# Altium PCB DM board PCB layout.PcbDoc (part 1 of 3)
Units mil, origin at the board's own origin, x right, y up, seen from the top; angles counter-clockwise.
Board outline 4444 x 6127 mil, 2 copper layers (Top Layer, Bottom Layer); 112 components, 94 nets, 2801 pads, 141 vias.
Unrouted connection lines stored in the file: 2.
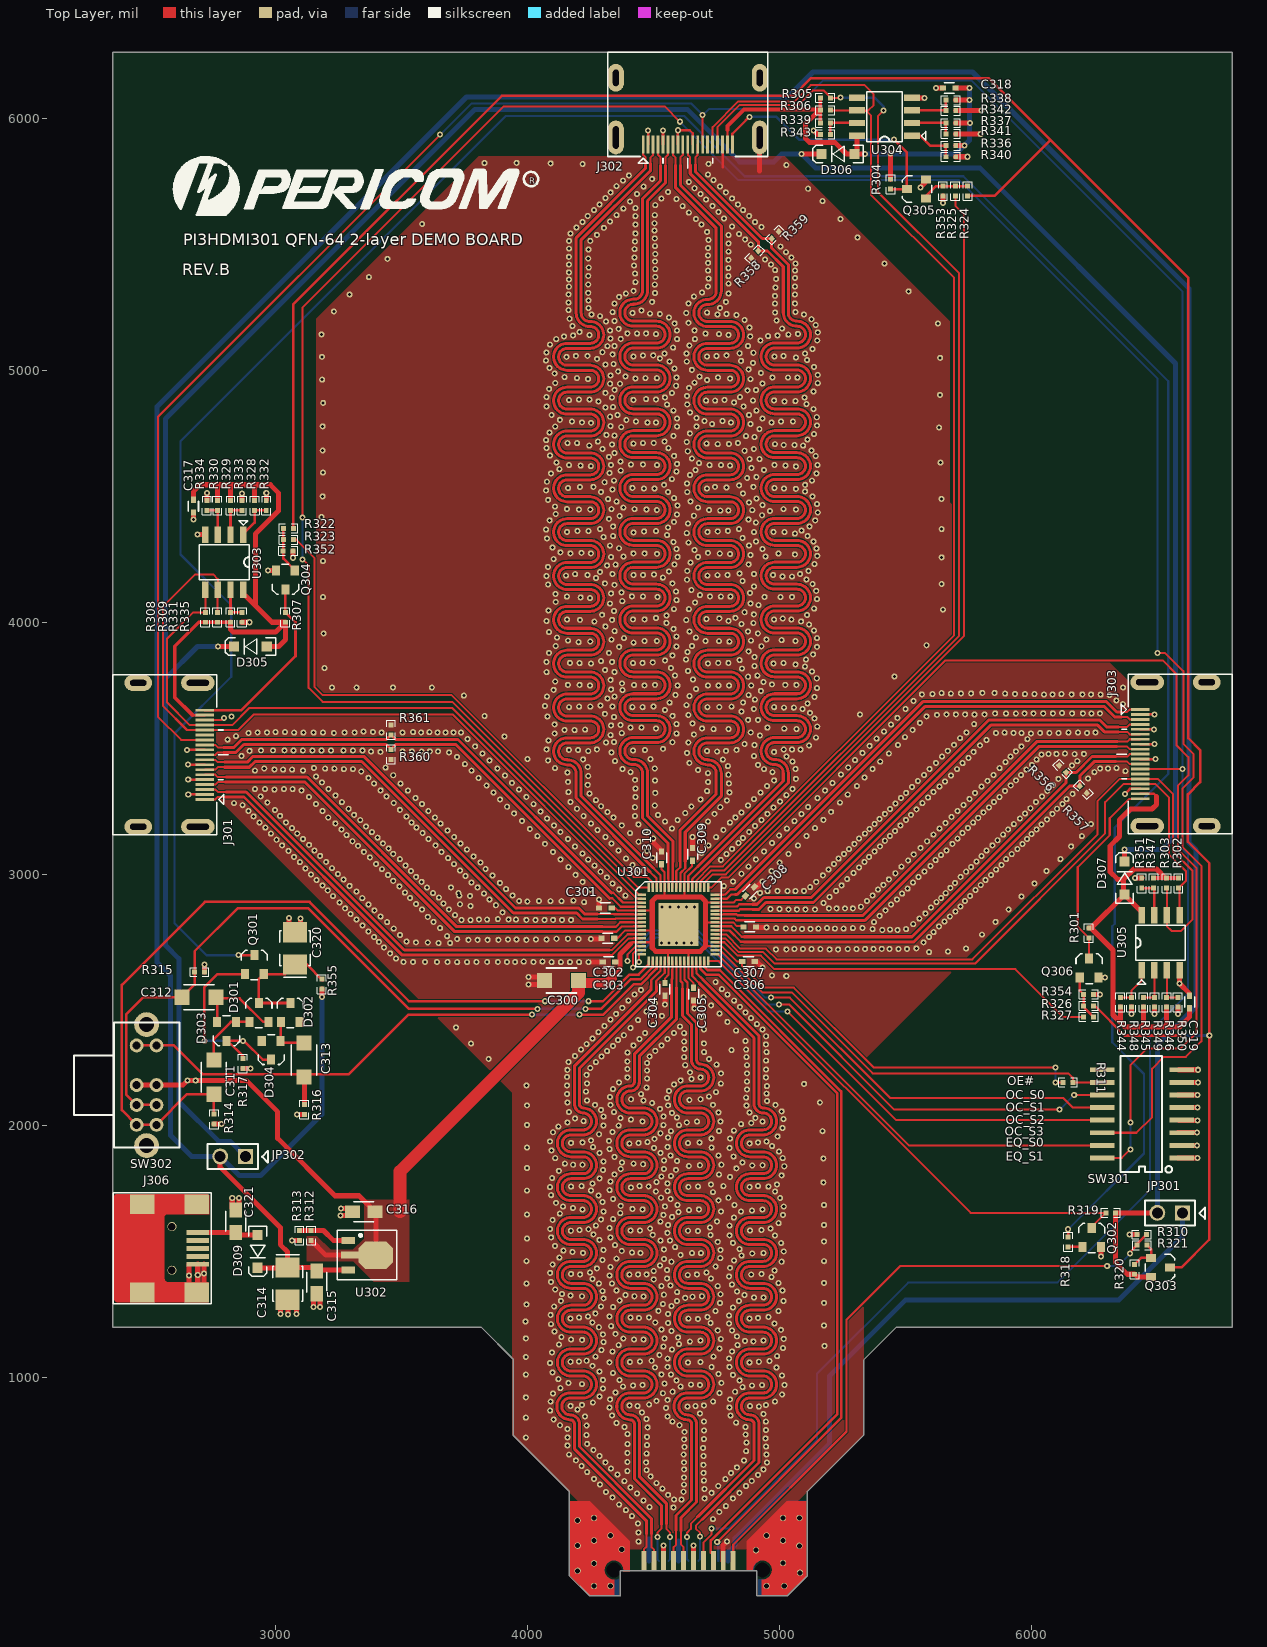
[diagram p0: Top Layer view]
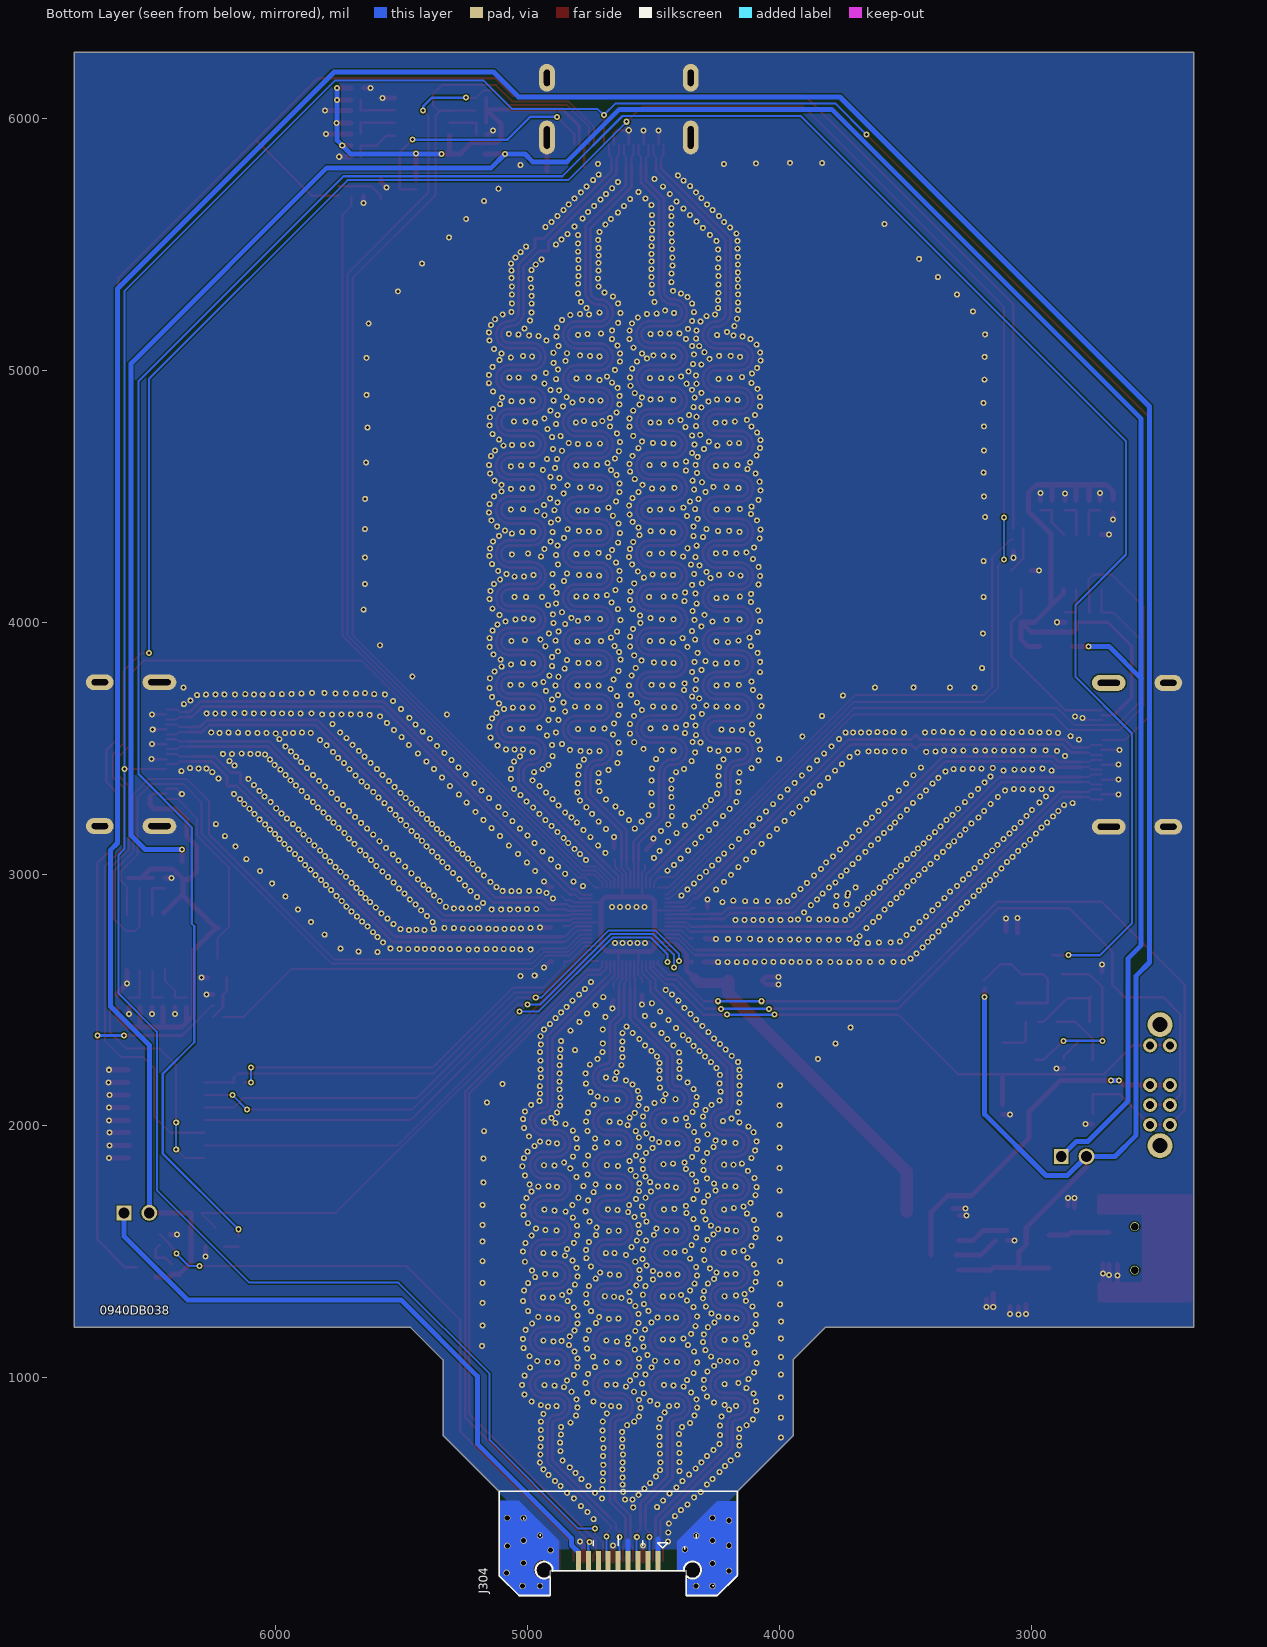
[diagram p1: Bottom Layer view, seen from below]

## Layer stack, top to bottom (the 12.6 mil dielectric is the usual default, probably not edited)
Top Layer: signal copper 1.4
Dielectric: dielectric 12.6, FR-4, Dk 4.8
Bottom Layer: signal copper 1.4

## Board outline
4166,216 4166,550 3944,772 3944,1074 3818,1200 2355,1200 2355,6262 6799,6262 6799,1200 5464,1200 5335,1071 5335,772 5112,549 5112,215 5032,135 4910,135 4910,234 4370,234 4370,136 4369,135 4247,135

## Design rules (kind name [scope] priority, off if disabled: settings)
Clearance [All] p1: gap=5
ComponentClearance [All] p1 off: gap=0 collisioncheckmode=3 verticalgap=0
DiffPairsRouting [All] p1: maxlimit=10 minlimit=8 mostfreqgap=10 toplayer_maxgap=8 toplayer_prefgap=8 bottomlayer_maxgap=8 bottomlayer_prefgap=8 maxuncoupledlength=500
HoleSize [All] p1: absolutevalues=TRUE maxlimit=300 minlimit=1 maxpercent=80.000 minpercent=20.000
PlaneConnect [All] p1: planeconnectstyle=Direct reliefexpansion=20 reliefentries=4 reliefconductorwidth=10 reliefairgap=10
PolygonConnect [All] p1: connectstyle=Direct reliefconductorwidth=10 reliefentries=4 polygonreliefangle="90 Angle"
RoomDefinition "301 (QFN-64) HDMI-HDMI" [InComponentClass('301 (QFN-64) HDMI-HDMI ')] p1: confinementstyle=ConfineIn formatcopy=TRUE lockcomponents=FALSE outline 35,830 43440,830 43440,12870 35,12870
RoutingVias [All] p1: holewidth=28 width=50 viastyle="Through Hole" minholewidth=8 minwidth=10 maxholewidth=28 maxwidth=50
SolderMaskExpansion [All] p1: expansion=4
TestPointUsage [All] p1: valid=0 allowmultiple=FALSE
Testpoint [All] p1: side=15 testpointundercomponent=TRUE minsize=40 maxsize=100 preferedsize=60 minholesize=0 maxholesize=40 preferedholesize=32 testpointgrid=1 style=1023 order=0123456789
Width [All] p1: maxlimit=100 minlimit=6 preferedwidth=10
15 further rules are at their usual default settings.

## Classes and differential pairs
differential pair NewDifferentialPair16: +D33+ -D33-
differential pair NewDifferentialPair15: +D32+ -D32-
differential pair NewDifferentialPair14: +D31+ -D31-
differential pair NewDifferentialPair13: +D3+ -D3-
differential pair NewDifferentialPair12: +D23+ -D23-
differential pair NewDifferentialPair11: +D22+ -D22-
differential pair NewDifferentialPair10: +D21+ -D21-
differential pair NewDifferentialPair9: +D2+ -D2-
differential pair NewDifferentialPair8: +D13+ -D13-
differential pair NewDifferentialPair7: +D12+ -D12-
differential pair NewDifferentialPair6: +D11+ -D11-
differential pair NewDifferentialPair5: +D1+ -D1-
differential pair NewDifferentialPair4: +D03+ -D03-
differential pair NewDifferentialPair3: +D02+ -D02-
differential pair NewDifferentialPair2: +D01+ -D01-
differential pair NewDifferentialPair1: +D0+ -D0-

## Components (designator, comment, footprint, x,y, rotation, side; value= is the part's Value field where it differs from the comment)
C300 "10U" CC_1206 4136,2577 r180 top
C301 "10n" CAP@CC_0402 4310,2865 r180 top
C302 "10n" CAP@CC_0402 4320,2745 r180 top
C303 "10n" CAP@CC_0402 4324,2651 r180 top
C304 "10n" CAP@CC_0402 4546,2542 r270 top
C305 "10n" CAP@CC_0402 4660,2523 r270 top
C306 "10n" CAP@CC_0402 4878,2652 r0 top
C307 "10n" CAP@CC_0402 4883,2790 r0 top
C308 "10n" CAP@CC_0402 4884,2931 r45 top
C309 "10n" CAP@CC_0402 4656,3078 r90 top
C310 "10n" CAP@CC_0402 4533,3064 r90 top
C311 "9.4u" CAP@CC_1206 2756,2193.5 r90 top
C312 "9.4u" CAP@CC_1206 2697,2511 r0 top
C313 "9.4u" CAP@CC_1206 3114,2262 r90 top
C314 "22u" CAP@CT_3528 3049,1374 r270 top
C315 "1u" CAP@CC_0805 3165,1379 r90 top
C316 "1u" CAP@CC_0805 3351,1659 r0 top
C317 "0.1u" CAP@CC_0402 2675,4460 r270 top
C318 "0.1u" CAP@CC_0402 5675,6120 r180 top
C319 "0.1u" CAP@CC_0402 6629,2492 r90 top
C320 "47u" CAP@CT_3528 3078,2705 r90 top
C321 "4.7u" CAP@CC_0805 2843,1622 r90 top
D301 "BAW56" DA@SOT-23-DD 2897,2413 r0 top
D302 "BAW56" DA@SOT-23-DD 3022,2413 r0 top
D303 "BAV70" DK@SOT-23-DD 2844,2413 r180 top
D304 "BAV70" DK@SOT-23-DD 3021,2338 r180 top
D305 "B0520LW" D@SOD-123 2901,3903 r180 top
D306 "B0520LW" D@SOD-123 5233,5858 r180 top
D307 "B0520LW" D@SOD-123 6371,2984 r90 top
D309 "B0520LW" D@SOD-123 2930,1502 r270 top
J301 "HDMI-R" HDMI_R@HDMI_R 2735,3296 r270 top
J302 "HDMI-R" HDMI_R@HDMI_R 4460,5881 r180 top
J303 "HDMI-R" HDMI_R@HDMI_R 6418,3653 r90 top
J304 "HDMI-T" HDMI_T@HDMI_T 4640,274 r90 bottom
J306 "Mini USB 2.0 Type B Female" USB_B_MINI@USB_B_MINI 2383,1514 r0 top
JP301 "CON 2" PLUG-2PIN@2PIN-100 6601,1655 r180 top
JP302 "CON 2" PLUG-2PIN@2PIN-100 2881,1879 r180 top
Q301 "MMBT3906" Q(PNP)@SOT-23 2879,2603 r0 top
Q302 "MMBT3904" Q(NPN)@SOT-23 6203,1520 r0 top
Q303 "MMBT3906" Q(PNP)@SOT-23 6476,1476 r270 top
Q304 "MMBT3904" Q(NPN)@SOT-23 3077,4205 r180 top
Q305 "MMBT3904" Q(NPN)@SOT-23 5582,5681 r90 top
Q306 "MMBT3904" Q(NPN)@SOT-23 6193,2589 r0 top
R301 "1K" RES@R_0402 6229,2766 r90 top
R302 "47K" RES@R_0402 6585,2964 r270 top
R303 "47K" RES@R_0402 6538,2964 r270 top
R304 "1K" RES@R_0402 5442,5738 r90 top
R305 "47K" RES@R_0402 5183,6081 r0 top
R306 "47K" RES@R_0402 5183,6032 r0 top
R307 "1K" RES@R_0402 3040,4019 r270 top
R308 "47K" RES@R_0402 2722,4019 r90 top
R309 "47K" RES@R_0402 2770,4019 r90 top
R310 "10K" RES@R_0402 6439,1569 r0 top
R311 "47K" RES@R_0402 6146,2173 r0 top
R312 "NP" RES@R_0402 3142,1565 r270 top
R313 "0" RES@R_0402 3096,1565 r270 top
R314 "2.7K" RES@R_0402 2757,2027 r90 top
R315 "2.7K" RES@R_0402 2699,2611 r180 top
R316 "2.7K" RES@R_0402 3115,2065 r90 top
R317 "68K" RES@R_0402 2871,2248 r90 top
R318 "20K" RES@R_0402 6147,1540 r90 top
R319 "10K" RES@R_0402 6316,1655 r180 top
R320 "20K" RES@R_0402 6411,1431 r270 top
R321 "100K" RES@R_0402 6440,1527 r0 top
R322 "20K" RES@R_0402 3052,4372 r0 top
R323 "20K" RES@R_0402 3052,4327 r180 top
R324 "20K" RES@R_0402 5748,5711 r90 top
R325 "20K" RES@R_0402 5699,5711 r90 top
R326 "20K" RES@R_0402 6228,2477 r180 top
R327 "20K" RES@R_0402 6228,2433 r0 top
R328 "NP/47K" RES@R_0402 2918,4463 r270 top
R329 "NP/47K" RES@R_0402 2822,4463 r270 top
R330 "47K" RES@R_0402 2770,4463 r270 top
R331 "NP/47K" RES@R_0402 2822,4019 r90 top
R332 "47K" RES@R_0402 2964,4463 r90 top
R333 "47K" RES@R_0402 2867,4463 r90 top
R334 "NP/47K" RES@R_0402 2728,4463 r90 top
R335 "47K" RES@R_0402 2867,4019 r270 top
R336 "NP/47K" RES@R_0402 5681,5891 r180 top
R337 "NP/47K" RES@R_0402 5681,5981 r180 top
R338 "47K" RES@R_0402 5681,6072 r180 top
R339 "NP/47K" RES@R_0402 5183,5981 r0 top
R340 "47K" RES@R_0402 5681,5847 r0 top
R341 "47K" RES@R_0402 5681,5938 r0 top
R342 "NP/47K" RES@R_0402 5681,6030 r0 top
R343 "47K" RES@R_0402 5183,5936 r180 top
R344 "NP/47K" RES@R_0402 6354,2491 r90 top
R345 "NP/47K" RES@R_0402 6446,2491 r90 top
R346 "47K" RES@R_0402 6538,2491 r90 top
R347 "NP/47K" RES@R_0402 6486,2964 r270 top
R348 "47K" RES@R_0402 6398,2491 r270 top
R349 "47K" RES@R_0402 6490,2491 r270 top
R350 "NP/47K" RES@R_0402 6582,2491 r270 top
R351 "47K" RES@R_0402 6439,2964 r90 top
R352 "20K" RES@R_0402 3051,4283 r180 top
R353 "20K" RES@R_0402 5650,5711 r90 top
R354 "20K" RES@R_0402 6228,2522 r180 top
R355 "2K" RES@R_0402 3185,2563 r270 top
R356 "1.5K" RES@R_0402 6125,3417 r135 top
R357 "22K" RES@R_0402 6207,3335 r315 top
R358 "1.5K" RES@R_0402 4903,5459 r225 top
R359 "22K" RES@R_0402 4984,5536 r45 top
R360 "1.5K" RES@R_0402 3459,3475 r270 top
R361 "22K" RES@R_0402 3459,3572 r90 top
SW301 "DIP-8" SW_X8_Half_Pitch 6440,2048 r90 top
SW302 "SK-23D07" SWDP3T 2489,2162 r270 top
U301 "PI3HDMI301" QFN-64 4600,2800 r0 top
U302 "Regulator 1117" Pow_SOT_89 3344,1487 r270 top
U303 "AT24C02B" SOIC-8 2797,4238 r180 top
U304 "AT24C02B" SOIC-8 5418,6006 r90 top
U305 "AT24C02B" SOIC-8 6514,2727 r0 top
? "" PSC_LOGO3 2629.99,5632 r0 top

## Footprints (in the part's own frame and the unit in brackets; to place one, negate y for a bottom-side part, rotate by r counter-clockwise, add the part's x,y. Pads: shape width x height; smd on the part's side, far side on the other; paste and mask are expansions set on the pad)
CAP@CC_0402 [mil]
  rect 25x20 smd: 1(-25,0) 2(25,0)
  silkscreen extent -20,-20 20,20
CAP@CC_0805 [mil]
  rect 60x50 smd: 1(-45,0) 2(45,0)
  silkscreen extent -40,-40 40,40
CAP@CC_1206 [mil]
  rect 60x60 smd: 1(-67.5,0) 2(67.5,0)
  silkscreen extent -60,-50 60,50
CAP@CT_3528 [mil]
  rect 80x95 smd: 1(-64,0) 2(64,0)
  silkscreen extent -115,-60 69,60
CC_1206 [mil]
  rect 60x60 smd: 1(-67.5,0) 2(67.5,0)
  silkscreen extent -60,-50 60,50
D@SOD-123 [mil]
  rect 40x40 smd: 1(-65,0) 2(65,0)
  silkscreen extent -100,-35 100,35
DA@SOT-23-DD [mil]
  rect 32x40 smd: 1(0,0) 2(75,0) 3(37.5,75)
  silkscreen extent -15,-24 90,94
DK@SOT-23-DD [mil]
  rect 32.01x40 smd: 1(0,0) 2(75,0) 3(37.52,75)
  silkscreen extent -15,-24 90,94
HDMI_R@HDMI_R [mm]
  rect 0.28x1.838 smd: 1(0,-0.381) 2(-0.5,-0.381) 3(-1,-0.381) 4(-1.5,-0.381) 5(-2,-0.381) 6(-2.5,-0.381) 7(-3,-0.381) 8(-3.5,-0.381) 9(-4,-0.381) 10(-4.5,-0.381) 11(-5,-0.381) 12(-5.5,-0.381) 13(-6,-0.381) 14(-6.5,-0.381) 15(-7,-0.381) 16(-7.5,-0.381) 17(-8,-0.381) 18(-8.5,-0.381) 19(-9,-0.381)
  oval 1.6x3.4 hole 0.6 slot 2.25 at 90 deg: 20(-11.75,-1.08) 21(2.75,-1.08)
  oval 1.6x2.8 hole 0.6 slot 1.65 at 90 deg: 22(-11.75,-7.09) 23(2.75,-7.09)
  silkscreen extent -12.55,-9.68 3.56,2
HDMI_T@HDMI_T [mm]
  rect 2x0.5 smd far side: 1(0,-4.5) 3(0,-3.5) 5(0,-2.5) 7(0,-1.5) 9(0,-0.5) 11(0,0.5) 13(0,1.5) 15(0,2.5) 17(0,3.5) 19(0,4.5)
  rect 2x0.5 smd: 2(0,-4) 4(0,-3) 6(0,-2) 8(0,-1) 10(0,0) 12(0,1) 14(0,2) 16(0,3) 18(0,4)
  round 0.635 hole 0.508: 20(-2.54,-9.525) 20(-2.54,-7.874) 20(-2.54,7.874) 20(-2.54,9.652) 20(-1.21,11.24) 20(-1.016,-11.176) 20(-0.254,-9.525) 20(-0.22,9.525) 20(1.067,6.807) 20(1.143,-6.731) 20(1.51,11.176) 20(1.524,-11.176) 20(2.032,-9.525) 20(2.032,9.525) 20(2.54,-7.874) 20(2.54,7.874) 20(4.064,-11.176) 20(4.318,-9.525) 20(4.318,9.525) 20(4.32,11.18)
  round 1 hole 1.5 unplated: 41(-0.94,7.46) 41(-0.93,-7.51)
  Top Layer region: -0.976,6.605 -0.875,6.592 -0.623,6.625 -0.388,6.723 -0.187,6.877 -0.032,7.079 0.065,7.314 0.099,7.566 0.065,7.818 -0.032,8.053 -0.187,8.254 -0.388,8.409 -0.623,8.506 -0.875,8.54 -1.127,8.506 -1.362,8.409 -1.564,8.254 -1.718,8.053 -1.816,7.818 -1.849,7.566 -1.85,7.092 -1.92,6.86 -3.46,6.888 -3.465,10.009 -1.484,11.991 6.06,11.991 6.06,10.009 2.021,5.971 -0.976,5.971 -0.976,6.606
  Top Layer region: -1.017,-6.575 -0.917,-6.561 -0.665,-6.595 -0.43,-6.692 -0.228,-6.847 -0.073,-7.048 0.024,-7.283 0.057,-7.535 0.024,-7.787 -0.073,-8.022 -0.228,-8.224 -0.43,-8.378 -0.665,-8.476 -0.917,-8.509 -1.169,-8.476 -1.403,-8.378 -1.605,-8.224 -1.76,-8.022 -1.857,-7.787 -1.89,-7.535 -1.851,-7.141 -1.831,-7.081 -1.941,-6.829 -3.501,-6.861 -3.506,-9.979 -1.525,-11.96 6.019,-11.96 6.019,-9.979 1.98,-5.94 -1.017,-5.94 -1.017,-6.575
  Bottom Layer region: -1.04,-6.565 -0.939,-6.551 -0.687,-6.585 -0.452,-6.682 -0.251,-6.837 -0.096,-7.038 0.001,-7.273 0.034,-7.525 0.001,-7.777 -0.096,-8.012 -0.251,-8.214 -0.452,-8.368 -0.687,-8.466 -0.939,-8.499 -1.191,-8.466 -1.426,-8.368 -1.628,-8.214 -1.783,-8.012 -1.88,-7.777 -1.913,-7.525 -1.907,-7.479 -1.904,-7.479 -3.529,-7.479 -3.529,-9.969 -1.548,-11.95 5.996,-11.95 5.996,-9.969 1.957,-5.93 -1.04,-5.93 -1.04,-6.565
  Bottom Layer region: -1.027,6.492 -0.926,6.479 -0.674,6.512 -0.439,6.609 -0.237,6.764 -0.083,6.965 0.015,7.2 0.048,7.452 0.015,7.704 -0.083,7.939 -0.237,8.141 -0.439,8.296 -0.674,8.393 -0.926,8.426 -1.178,8.393 -1.413,8.296 -1.614,8.141 -1.769,7.939 -1.866,7.704 -1.9,7.452 -1.894,7.407 -1.89,7.407 -3.516,7.407 -3.516,9.896 -1.535,11.877 6.009,11.877 6.009,9.896 1.971,5.857 -1.027,5.857 -1.027,6.492
  silkscreen extent -3.5,-12 7,12
PLUG-2PIN@2PIN-100 [mm] "Pin Header 2x1 Pitch 2.54mm"
  rect 1.5x1.5 hole 1.1: 1(0,0)
  round 1.6 hole 1.1: 2(2.54,0)
  silkscreen extent -2.27,-1.27 3.81,1.27
Pow_SOT_89 [mm] "SOT-89; Body 4.6 x 4.25 mm, inc. leads (LxW max)"
  rect 0.7x1.35 smd: 1(-1.5,-1.388) 3(1.5,-1.388)
  oct 2.8x3.5 smd: 2(0,1.388)
  rect 0.7x1.9 smd: 2(0,-1.163)
  silkscreen extent -2.5,-2.51 2.5,3.49
PSC_LOGO3 [mil]
  silkscreen extent -32,-15 1413,214
Q(NPN)@SOT-23 [mil]
  rect 32.01x40 smd: 1(0,0) 2(75,0) 3(37.48,75)
  silkscreen extent -15,-24 90,94
Q(PNP)@SOT-23 [mil]
  rect 32x40 smd: 1(0,0) 2(75,0) 3(37.5,75)
  silkscreen extent -15,-24 90,94
QFN-64 [mm]
  rect 0.9x0.25 smd: 1(-3.7,3) 2(-3.7,2.6) 3(-3.7,2.2) 4(-3.7,1.8) 5(-3.7,1.4) 6(-3.7,1) 7(-3.7,0.6) 8(-3.7,0.2) 9(-3.7,-0.2) 10(-3.7,-0.6) 11(-3.7,-1) 12(-3.7,-1.4) 13(-3.7,-1.8) 14(-3.7,-2.2) 15(-3.7,-2.6) 16(-3.7,-3) 33(3.7,-3) 34(3.7,-2.6) 35(3.7,-2.2) 36(3.7,-1.8) 37(3.7,-1.4) 38(3.7,-1) 39(3.7,-0.6) 40(3.7,-0.2) 41(3.7,0.2) 42(3.7,0.6) 43(3.7,1) 44(3.7,1.4) 45(3.7,1.8) 46(3.7,2.2) 47(3.7,2.6) 48(3.7,3)
  rect 0.25x0.9 smd: 17(-3,-3.7) 18(-2.6,-3.7) 19(-2.2,-3.7) 20(-1.8,-3.7) 21(-1.4,-3.7) 22(-1,-3.7) 23(-0.6,-3.7) 24(-0.2,-3.7) 25(0.2,-3.7) 26(0.6,-3.7) 27(1,-3.7) 28(1.4,-3.7) 29(1.8,-3.7) 30(2.2,-3.7) 31(2.6,-3.7) 32(3,-3.7) 49(3,3.7) 50(2.6,3.7) 51(2.2,3.7) 52(1.8,3.7) 53(1.4,3.7) 54(1,3.7) 55(0.6,3.7) 56(0.2,3.7) 57(-0.2,3.7) 58(-0.6,3.7) 59(-1,3.7) 60(-1.4,3.7) 61(-1.8,3.7) 62(-2.2,3.7) 63(-2.6,3.7) 64(-3,3.7)
  rect 4.064x4.318 smd: 65(0.01,0)
  silkscreen extent -4.3,-4.28 4.31,4.28
RES@R_0402 [mm]
  rect 0.5x0.5 smd: 1(-0.5,0) 2(0.5,0)
  silkscreen extent -0.95,-0.45 0.95,0.45
SOIC-8 [mm]
  rect 0.65x1.65 smd: 1(-1.905,-2.775) 2(-0.635,-2.775) 3(0.635,-2.775) 4(1.905,-2.775) 5(1.905,2.775) 6(0.635,2.775) 7(-0.635,2.775) 8(-1.905,2.775)
  silkscreen extent -2.51,-4.17 2.51,1.78
SW_X8_Half_Pitch [mm] "CHS-08TA"
  rect 0.5x2.5 smd: 1(-4.445,-4) 2(-3.175,-4) 3(-1.905,-4) 4(-0.635,-4) 5(0.635,-4) 6(1.905,-4) 7(3.175,-4) 8(4.445,-4) 9(4.445,4) 10(3.175,4) 11(1.905,4) 12(0.635,4) 13(-0.635,4) 14(-1.905,4) 15(-3.175,4) 16(-4.445,4)
  silkscreen extent -5.94,-3.04 5.85,2.16
SWDP3T [mm]
  round 1.4 hole 0.8: 1(-4,1) 2(0,1) 3(2,1) 4(4,1) 5(-4,-1) 6(0,-1) 7(2,-1) 8(4,-1)
  round 2.5 hole 1.5: 9(-6.1,0) 10(6.1,0)
  silkscreen extent -6.3,-7.3 6.3,3.3
USB_B_MINI@USB_B_MINI [mm]
  rect 2.3x0.5 smd: 1(7.85,1.6) 2(7.85,0.8) 3(7.85,0) 4(7.85,-0.8) 5(7.85,-1.6)
  rect 2.5x2 smd: 5(2.25,-4.45) 5(2.25,4.45) 5(7.75,-4.45) 5(7.75,4.45)
  round 0.9 hole 0.762 unplated: 10(5.25,-2.2) 11(5.25,2.2)
  Top Layer region: 1.58,5.45 -0.35,5.45 -0.438,5.432 -0.513,5.383 -0.562,5.308 -0.58,5.22 -0.58,5.22 -0.58,-5.09 -0.553,-5.224 -0.477,-5.337 -0.364,-5.413 -0.23,-5.44 -0.23,-5.44 8.81,-5.44 8.875,-5.427 8.93,-5.39 8.967,-5.335 8.98,-5.27 8.98,-5.27 8.98,-3.59 8.968,-3.529 8.933,-3.477 8.881,-3.442 8.82,-3.43 8.82,-3.43 4.93,-3.43 4.758,-3.396 4.612,-3.298 4.514,-3.152 4.48,-2.98 4.48,-2.98 4.48,3.17 4.5,3.269 4.556,3.354 4.641,3.41 4.74,3.43 4.74,3.43 8.93,3.43 8.964,3.437 8.994,3.456 9.013,3.486 9.02,3.52 9.02,3.52 9.02,5.26 9.004,5.34 8.958,5.408 8.89,5.454 8.81,5.47 8.81,5.47 1.6,5.47 1.592,5.468 1.586,5.464 1.582,5.458 1.58,5.45
  silkscreen extent -0.65,-5.59 9.19,5.6

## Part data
C301 C302 C303 C304 C305 C306 C307 C308 C309 C310 C311 C312 C313 C315 C316 C317 C318 C319: library part "CAP NP_Dup1"
C314 C320: library part CAP
C321: library part "CAP NP"
D301 D302: library part "DI dual com A"
D303 D304: library part "DI dual com C BAV70"
D305 D306 D307 D309: library part 1N5817M/CYL
J301 J302 J303 J304: library part "CON HDMI19_A pin mame"
J306: library part "USB 2_0.0 Mini B Female"
Q301 Q303: library part "T PNP BEC"
Q302 Q304 Q305 Q306: library part "T NPN BEC"
R301 R302 R303 R304 R305 R306 R307 R308 R309 R310 R311 R312 R313 R317 R318 R319 R320 R321 R322 R323 R324 R325 R326 R327 R328 R329 R330 R331 R332 R333 R334 R335 R336 R337 R338 R339 R340 R341 R342 R343 R344 R345 R346 R347 R348 R349 R350 R351 R352 R353 R354 R355 R356 R357 R358 R359 R360 R361: library part R
R314 R315 R316: library part 11K_0
SW301: library part "SW DIP-8/SM_0"
SW302: library part SW_EG2310A
U301: library part PI3HDMI301_8
U302: library part "Reg 117 1117 8117_0"
U303 U304 U305: library part AT24C02_0

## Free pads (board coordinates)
  round 24 hole 12: 0(4948,2356) 0(5104,2860) 1(4844,2473) 1(5070,2860) 2(4934,2383) 2(5037,2860) 3(4772,2543) 3(5001,2861) 4(4888,2428) 4(4965,2861) 5(4911,2404) 6(4748,2571) 7(3955,2819) 7(4821,2497) 8(4033,2818) 8(4866,2451) 9(4069,2818) 9(4795,2521) 10(4103,2818) 10(5544,2705) 11(4138,2818) 11(5507,2703) 12(4174,2818) 12(5438,2703) 13(3996,2818) 13(5272,2702) 14(2894,3560) 14(5200,2701) 15(3189,3561) 15(5128,2702) 16(3232,3560) 16(5060,2702) 17(3275,3562) 17(4987,2701) 18(3315,3562) 18(5407,2703) 19(3505,3561) 19(5473,2702) 20(2844,3547) 20(5307,2702) 21(2930,3562) 21(5341,2703) 22(3038,3563) 22(5374,2703) 23(3075,3561) 23(5234,2701) 24(3152,3561) 24(5163,2702) 25(3001,3563) 25(5094,2702) 26(2991,3491) 26(5028,2701) 27(2898,3489) 28(2943,3491) 29(2811,3533) 30(2866,3469) 31(2967,3562) 32(3111,3561) 34(2996,3415) 35(3031,3414) 36(3067,3414) 37(3110,3411) 38(3153,3421) 39(2956,3419) 40(2919,3410) 41(2836,3281) 42(5099,2167) 43(5161,2093) 44(5172,1979) 45(5175,1871) 46(5175,1776) 47(5178,1686) 48(5178,1607) 49(5178,1542) 50(5178,1463) 51(5178,1377) 52(5178,1298) 53(5178,1208) 54(5180,1127) 55(3994,1083) 56(3994,1157) 57(3994,1013) 58(3994,923) 59(3994,842) 60(3994,763) 61(3993,1224) 62(3997,1292) 63(3997,1374) 64(3997,1463) 65(3999,1553) 66(3999,1648) 67(3999,1743) 68(3999,1833) 69(3999,1914) 70(3999,2004) 71(3999,2082) 72(3997,2161) 73(5742,2704) 74(5805,2759) 75(5859,2810) 76(5911,2859) 77(5961,2911) 78(6013,2963) 79(6061,3012) 80(6116,3059) 81(6159,3110) 82(6201,3150) 83(6237,3198) 84(5595,2690) 85(5670,2692) 86(5999,3558) 87(6036,3560) 88(6072,3560) 89(6109,3560) 90(6148,3561) 91(6186,3561) 92(6222,3560) 93(6255,3562) 96(5939,3637) 97(5974,3638) 98(6009,3638) 99(6048,3638) 100(6086,3638) 101(6123,3639) 102(6163,3638) 103(6205,3638) 104(6239,3637) 105(6273,3638) 106(5815,3634) 107(5320,3633) 108(5457,3784) 109(5645,4369) 111(5645,4257) 112(5644,4489) 113(5640,4633) 114(5635,4772) 115(5638,4902) 116(5172,5671) 117(5115,5720) 118(5028,5814) 119(4720,5819) 120(5418,5423) 121(3185,5053) 122(3188,4777) 123(3189,4593) 124(3188,4681) 125(3190,4870) 126(3186,4962) 127(3371,5369) 128(3583,5580) 129(3830,5822) 130(4093,5821) 131(4220,5818) 132(3958,5823) 133(3188,4499) 134(3189,4242) 135(3192,3955) 136(3189,4099) 137(3225,3740) 138(3183,4417) 139(3195,3817) 140(3323,3740) 141(3467,3741) 142(3748,3708) 143(3621,3740) 144(3831,3627) 145(3909,3546) 148(4001,3456) 149(5311,5527) 150(5243,5600) 151(5645,4151) 152(5650,4049) 153(5585,3908) 154(3183,5142) 155(3232,5233) 156(3295,5300) 157(3445,5442) 158(5514,5313) 159(5630,5185) 160(5639,5049) 161(6365,3740) 162(3717,2391) 163(3777,2327) 164(3847,2266) ""(2870,3273) ""(2893,3250) ""(2914,3229) ""(2919,3337) ""(2937,3204) ""(2942,3308) ""(2959,3337) ""(2960,3184) ""(2968,3284) ""(2982,3160) ""(2996,3335) ""(2998,3254) ""(3005,3136) ""(3019,3231) ""(3027,3114) ""(3034,3337) ""(3036,3491) ""(3042,3205) ""(3052,3092) ""(3066,3182) ""(3069,3337) ""(3072,3490) ""(3074,3068) ""(3087,3161) ""(3097,3047) ""(3104,3332) ""(3109,3490) ""(3110,3139) ""(3119,3022) ""(3133,3306) ""(3134,3116) ""(3141,2998) ""(3147,3490) ""(3155,3093) ""(3161,3278) ""(3162,3387) ""(3164,2976) ""(3178,3072) ""(3183,3490) ""(3185,3364) ""(3187,2955) ""(3187,3250) ""(3198,3418) ""(3202,3048) ""(3208,2935) ""(3210,3224) ""(3211,3338) ""(3221,3490) ""(3225,3023) ""(3229,2912) ""(3234,3418) ""(3238,3201) ""(3239,3312) ""(3248,3000) ""(3255,2887) ""(3262,3177) ""(3264,3285) ""(3270,3490) ""(3271,2978) ""(3272,3416) ""(3277,2864) ""(3283,3154) ""(3291,3259) ""(3295,2953) ""(3299,2841) ""(3306,3130) ""(3308,3416) ""(3308,3490) ""(3313,3235) ""(3322,2819) ""(3322,2930) ""(3328,3112) ""(3337,3214) ""(3341,3407) ""(3345,2904) ""(3346,2796) ""(3346,3490) ""(3350,3565) ""(3351,3088) ""(3360,3189) ""(3369,2772) ""(3369,3382) ""(3370,2879) ""(3375,3066) ""(3380,3486) ""(3383,3166) ""(3387,3564) ""(3392,2750) ""(3392,3359) ""(3393,2856) ""(3400,3040) ""(3406,3144) ""(3411,2731) ""(3417,3485) ""(3418,2831) ""(3418,3332) ""(3422,3562) ""(3423,3019) ""(3427,3122) ""(3431,2709) ""(3438,3422) ""(3441,3308) ""(3444,2809) ""(3447,2996) ""(3450,3102) ""(3456,2685) ""(3468,2973) ""(3468,3080) ""(3468,3392) ""(3470,2783) ""(3470,3282) ""(3479,2664) ""(3492,2951) ""(3494,3059) ""(3494,3255) ""(3495,2758) ""(3497,3359) ""(3505,3487) ""(3508,2651) ""(3514,2926) ""(3517,3034) ""(3520,3228) ""(3521,2732) ""(3526,3331) ""(3535,2905) ""(3538,3012) ""(3541,3204) ""(3542,3487) ""(3547,2651) ""(3547,3563) ""(3557,3302) ""(3558,2729) ""(3559,2881) ""(3559,2989) ""(3560,3184) ""(3579,3562) ""(3581,2969) ""(3581,3486) ""(3582,2859) ""(3582,3278) ""(3585,3163) ""(3594,2651) ""(3602,2946) ""(3605,2728) ""(3605,2830) ""(3607,3250) ""(3608,3139) ""(3611,3563) ""(3613,3487) ""(3626,2924) ""(3628,2810) ""(3633,3224) ""(3636,3114) ""(3641,2651) ""(3644,3562) ""(3646,3487) ""(3648,2726) ""(3649,2906) ""(3654,2785) ""(3656,3200) ""(3659,3088) ""(3667,2883) ""(3676,3562) ""(3682,2753) ""(3684,2651) ""(3684,3173) ""(3686,3063) ""(3689,2860) ""(3690,3483) ""(3694,2726) ""(3697,2947) ""(3707,3562) ""(3709,3039) ""(3710,3147) ""(3713,2837) ""(3721,3465) ""(3722,2650) ""(3722,2742) ""(3727,2924) ""(3730,2914) ""(3733,2880) ""(3733,3014) ""(3735,3121) ""(3737,3561) ""(3739,2818) ""(3752,3436) ""(3755,2992) ""(3760,3097) ""(3761,2650) ""(3763,3536) ""(3766,2739) ""(3773,2913) ""(3775,2817) ""(3775,2873) ""(3778,2966) ""(3779,3410) ""(3787,3070) ""(3793,3507) ""(3798,2651) ""(3803,2739) ""(3803,2947) ""(3807,3381) ""(3808,2820) ""(3814,3046) ""(3822,3478) ""(3828,2922) ""(3835,3020) ""(3839,3351) ""(3841,2651) ""(3841,2819) ""(3843,2739) ""(3850,2899) ""(3850,3451) ""(3862,2994) ""(3866,3323) ""(3875,2876) ""(3881,3419) ""(3883,2651) ""(3883,2821) ""(3885,2739) ""(3891,2965) ""(3892,3296) ""(3902,2848) ""(3911,3391) ""(3916,2940) ""(3919,2651) ""(3920,3267) ""(3923,2740) ""(3926,2820) ""(3939,3362) ""(3942,2915) ""(3948,3241) ""(3952,2651) ""(3957,2740) ""(3967,3335) ""(3968,2893) ""(3979,3211) ""(3986,2652) ""(3996,2739) ""(3996,3306) ""(4000,2891) ""(4010,3179) ""(4024,2651) ""(4025,3277) ""(4034,2740) ""(4040,3150) ""(4046,2893) ""(4053,3248) ""(4060,2652) ""(4070,3120) ""(4070,3667) ""(4074,5038) ""(4075,4367) ""(4075,4523) ""(4075,4722) ""(4076,3842) ""(4076,4183) ""(4076,5070) ""(4077,2740) ""(4077,3495) ""(4077,3801) ""(4077,4004) ""(4077,4691) ""(4077,4856) ""(4077,4893) ""(4078,3704) ""(4078,4332) ""(4078,4557) ""(4079,3220) ""(4080,3625) ""(4082,4219) ""(4083,3451) ""(4083,4149) ""(4083,4485) ""(4084,3530) ""(4084,4046) ""(4086,3878) ""(4086,3960) ""(4087,4926) ""(4088,4752) ""(4088,5009) ""(4089,4404) ""(4090,1059) ""(4090,1757) ""(4090,1939) ""(4090,4661) ""(4090,5101) ""(4091,870) ""(4091,1417) ""(4091,1591) ""(4092,2892) ""(4093,906) ""(4093,1250) ""(4094,1213) ""(4094,1381) ""(4094,4590) ""(4095,1558) ""(4095,1725) ""(4096,1903) ""(4097,2650) ""(4097,4822) ""(4098,1101) ""(4099,1793) ""(4100,1022) ""(4100,4296) ""(4101,1450) ""(4101,1627) ""(4102,938) ""(4102,1975) ""(4102,3088) ""(4105,835) ""(4105,3731) ""(4105,4250) ""(4106,3193) ""(4107,1283) ""(4108,1184) ""(4109,3558) ""(4109,3594) ""(4109,4987) ""(4110,1524) ""(4110,3420) ""(4110,4458) ""(4111,1351) ""(4111,1872) ""(4111,3764) ""(4111,4776) ""(4111,4949) ""(4112,4112) ""(4113,3905) ""(4113,4080) ""(4113,4429) ""(4114,1695) ""(4115,5123) ""(4116,2743) ""(4116,4633) ""(4118,3938) ""(4123,995) ""(4123,1997) ""(4125,1822) ""(4126,1132) ""(4127,1477) ""(4127,4607) ""(4129,1652) ""(4129,4803) ""(4130,812) ""(4131,959) ""(4131,3167) ""(4131,4277) ""(4132,3058) ""(4133,1306) ""(4133,2650) ""(4135,1162) ""(4136,2892) ""(4138,1333) ""(4142,1680) ""(4143,1505) ""(4146,5134) ""(4148,3572) ""(4148,4972) ""(4149,1850) ""(4154,4184) ""(4156,5053) ""(4157,4101) ""(4157,4449) ""(4158,2127) ""(4158,2161) ""(4158,2195) ""(4158,4010) ""(4158,4358) ""(4159,732) ""(4159,797) ""(4159,2014) ""(4159,2093) ""(4159,2223) ""(4159,3403) ""(4160,764) ""(4160,4710) ""(4161,2743) ""(4161,3139) ""(4161,3751) ""(4162,3366) ""(4162,3926) ""(4162,4532) ""(4163,980) ""(4163,3027) ""(4163,3325) ""(4164,2254) ""(4164,5238) ""(4164,5268) ""(4164,5301) ""(4165,2055) ""(4165,3493) ""(4165,5331) ""(4165,5360) ""(4165,5388) ""(4165,5419) ""(4165,5450) ""(4166,695) ""(4166,3662) ""(4166,4623) ""(4166,4881) ""(4166,5482) ""(4166,5513) ""(4168,5204) ""(4169,2650) ""(4169,3838) ""(4171,1236) ""(4171,3286) ""(4171,4273) ""(4171,5542) ""(4172,889) ""(4172,1064) ""(4172,1327) ""(4173,1584) ""(4174,1152) ""(4174,1413) ""(4174,1759) ""(4174,1933) ""(4177,4796) ""(4179,1500) ""(4179,5175) ""(4181,1674) ""(4182,1846) ""(4182,5138) ""(4183,2894) ""(4188,3571) ""(4189,2278) ""(4189,3109) ""(4190,2030) ""(4190,4190) ""(4192,2997) ""(4193,673) ""(4193,5057) ""(4195,5566) ""(4197,3259) ""(4197,4968) ""(4198,4710) ""(4199,874) ""(4199,4362) ""(4202,3492) ""(4204,2742) ""(4204,3920) ""(4205,1065) ""(4205,4447) ""(4205,4883) ""(4206,1239) ""(4206,2650) ""(4206,3664) ""(4208,1587) ""(4208,3751) ""(4208,3837) ""(4208,5152) ""(4209,4009) ""(4209,4536) ""(4210,1411) ""(4212,4098) ""(4212,4621) ""(4213,2303) ""(4215,4275) ""(4216,650) ""(4216,1761) ""(4217,893) ""(4217,975) ""(4217,1324) ""(4217,4793) ""(4218,1151) ""(4219,1668) ""(4219,1846) ""(4219,1935) ""(4219,3081) ""(4219,5588) ""(4220,2969) ""(4221,1496) ""(4222,3455) ""(4224,2019) ""(4224,3230) ""(4226,2888) ""(4229,847) ""(4230,3573) ""(4233,2136) ""(4235,773) ""(4236,811) ""(4236,1068) ""(4236,2203) ""(4236,2325) ""(4237,2101) ""(4237,2169) ""(4238,626) ""(4238,738) ""(4239,4187) ""(4239,5057) ""(4240,3354) ""(4240,3425) ""(4240,5612) ""(4241,1243) ""(4241,4965) ""(4242,3057) ""(4242,3389) ""(4242,3488) ""(4242,5307) ""(4242,5340) ""(4242,5374) ""(4242,5443) ""(4243,1590) ""(4243,2650) ""(4243,4361) ""(4243,5246) ""(4243,5277) ""(4243,5479) ""(4244,5407) ""(4246,4700) ""(4247,3319) ""(4247,4883) ""(4247,5139) ""(4249,1418) ""(4249,3748) ""(4249,4095) ""(4250,2230) ""(4250,3664) ""(4250,3923) ""(4250,4447) ""(4250,5513) ""(4251,2938) ""(4252,2742) ""(4252,4273) ""(4252,4619) ""(4253,1744) ""(4253,1943) ""(4253,3200) ""(4253,3835) ""(4253,4791) ""(4255,5221) ""(4258,1220) ""(4259,1048) ""(4259,1393) ""(4259,1771) ""(4259,2347) ""(4260,902) ""(4261,1916) ""(4262,714) ""(4262,1570) ""(4262,4537) ""(4265,599) ""(4265,5635) ""(4266,4002) ""(4267,3033) ""(4269,2084) ""(4270,1256) ""(4271,1084) ""(4272,1604) ""(4272,2253) ""(4272,3293) ""(4273,4175) ""(4276,1435) ""(4276,3495) ""(4276,5537) ""(4277,5045) ""(4279,3174) ""(4280,4716) ""(4282,2372) ""(4282,4876) ""(4283,1724) ""(4284,1201) ""(4284,1374) ""(4285,1967) ""(4286,1025) ""(4286,1548) ""(4287,690) ""(4287,926) ""(4287,1792) ""(4287,1893) ""(4287,5658) ""(4288,577) ""(4289,4199) ""(4289,4369) ""(4289,5214) ""(4290,3669) ""(4291,3009) ""(4292,1283) ""(4293,1629) ""(4293,2064) ""(4293,3269) ""(4293,3845) ""(4293,4517) ""(4294,1110) ""(4295,2276) ""(4297,4029) ""(4298,1468) ""(4298,5071) ""(4299,1344) ""(4299,1698) ""(4299,4687) ""(4300,958) ""(4300,992) ""(4300,1173) ""(4301,1825) ""(4302,1508) ""(4302,1859) ""(4302,2002) ""(4303,1142) ""(4303,1316) ""(4303,1660) ""(4303,2037) ""(4303,4337) ""(4304,5565) ""(4306,2397) ""(4307,4555) ""(4308,3636) ""(4308,4154) ""(4309,3810) ""(4310,665) ""(4310,3147) ""(4310,3983) ""(4310,4852) ""(4310,4910) ""(4310,5022) ""(4310,5683) ""(4312,547) ""(4313,3522) ""(4313,5193) ""(4314,4743) ""(4316,2987) ""(4317,2297) ""(4317,4225) ""(4318,3246) ""(4318,3697) ""(4318,5095) ""(4321,4488) ""(4324,1941) ""(4324,3878) ""(4324,4410) ""(4324,4656) ""(4326,882) ""(4326,1062) ""(4326,1244) ""(4327,1406) ""(4327,1595) ""(4327,1745) ""(4327,1908) ""(4327,4592) ""(4328,2115) ""(4328,4073) ""(4328,4303) ""(4329,915) ""(4329,4815) ""(4329,4946) ""(4329,5157) ""(4329,5590) ""(4330,1440) ""(4330,1557) ""(4330,1779) ""(4330,2084) ""(4330,2422) ""(4330,5125) ""(4331,3551) ""(4331,3771) ""(4331,4778) ""(4331,4979) ""(4331,5706) ""(4332,640) ""(4332,4624) ""(4333,1205) ""(4333,3590) ""(4333,3733) ""(4333,4114) ""(4333,4258) ""(4334,3121) ""(4334,3483) ""(4334,3930) ""(4334,4448) ""(4336,1374) ""(4336,4891) ""(4337,851) ""(4337,3842) ""(4337,4009) ""(4337,4705) ""(4338,526) ""(4338,1104) ""(4338,1976) ""(4338,3665) ""(4338,4191) ""(4338,4526) ""(4339,2962) ""(4339,5063) ""(4339,5230) ""(4340,1019) ""(4340,2146) ""(4340,2318) ""(4340,4853) ""(4341,1281) ""(4341,1630) ""(4341,1710) ""(4341,4341) ""(4341,4380) ""(4342,3225) ""(4343,5024) ""(4344,2055) ""(4344,3524) ""(4344,3623) ""(4344,4044) ""(4344,4561) ""(4346,1808) ""(4346,1877) ""(4346,3704) ""(4346,3802) ""(4346,4148) ""(4346,4671) ""(4346,4740) ""(4346,5096) ""(4346,5195) ""(4346,5264) ""(4347,3964) ""(4347,4922) ""(4348,1527) ""(4348,3448) ""(4350,942) ""(4350,1175) ""(4351,4228) ""(4353,2445) ""(4354,821) ""(4354,1347) ""(4354,1473) ""(4354,5730) ""(4355,4478) ""(4355,5615) ""(4358,616) ""(4358,4822) ""(4360,2341) ""(4361,4995) ""(4362,3093) ""(4363,1130) ""(4363,2001) ""(4363,5164) ""(4364,2173) ""(4364,4293) ""(4365,497) ""(4365,2939) ""(4365,3902) ""(4365,5291) ""(4366,991) ""(4367,1307) ""(4367,4421) ""(4368,4946) ""(4369,1654) ""(4370,2031) ""(4370,3592) ""(4370,4637) ""(4371,1683) ""(4371,1829) ""(4371,4601) ""(4371,5124) ""(4373,4774) ""(4374,4118) ""(4375,1504) ""(4375,3193) ""(4375,3559) ""(4376,1855) ""(4376,3757) ""(4377,2469) ""(4377,4083) ""(4378,3417) ""(4378,3730) ""(4380,965) ""(4380,5752) ""(4381,1156) ""(4381,4454) ""(4381,5641) ""(4382,4260) ""(4383,2360) ""(4384,3936) ""(4385,590) ""(4386,805) ""(4389,2914) ""(4390,1329) ""(4390,4975) ""(4391,475) ""(4391,5304) ""(4392,3061) ""(4393,4802) ""(4397,630) ""(4397,666) ""(4397,702) ""(4397,2193) ""(4397,2226) ""(4397,2256) ""(4397,5146) ""(4398,737) ""(4398,777) ""(4398,2291) ""(4401,2497) ""(4403,5773) ""(4405,1410) ""(4405,1930) ""(4406,891) ""(4407,1063) ""(4408,3162) ""(4408,5669) ""(4409,565) ""(4410,1239) ""(4410,1585) ""(4410,2389) ""(4410,3404) ""(4410,3581) ""(4411,1756) ""(4411,2025) ""(4411,4625) ""(4412,2106) ""(4415,451) ""(4415,4102) ""(4416,1497) ""(4417,1671) ""(4417,3662) ""(4417,4533) ""(4418,3036) ""(4418,5227) ""(4420,970) ""(4420,3490) ""(4420,3837) ""(4420,4011) ""(4421,2320) ""(4421,4273) ""(4421,4708) ""(4421,4882) ""(4421,5054) ""(4422,1850) ""(4422,3918) ""(4422,4187) ""(4422,4356) ""(4422,5315) ""(4424,1152) ""(4424,3750) ""(4424,5415) ""(4425,1324) ""(4425,5447) ""(4426,2522) ""(4426,4448) ""(4426,5480) ""(4427,3230) ""(4427,3265) ""(4427,5511) ""(4428,3374) ""(4428,5383) ""(4429,3306) ""(4429,3339) ""(4429,4967) ""(4429,5349) ""(4429,5543) ""(4429,5578) ""(4429,5611) ""(4429,5643) ""(4431,4796) ""(4435,5699) ""(4436,541) ""(4436,5145) ""(4438,888) ""(4439,422) ""(4440,1411) ""(4440,2420) ""(4441,386) ""(4441,3197) ""(4442,350) ""(4442,1933) ""(4442,3128) ""(4443,1238) ""(4444,3013) ""(4445,2345) ""(4446,1761) ""(4447,1065) ""(4447,1585) ""(4449,1496) ""(4451,2540) ""(4452,2126) ""(4453,3581) ""(4453,5237) ""(4455,863) ""(4457,2018) ""(4458,972) ""(4458,1669) ""(4458,3662) ""(4458,3838) ""(4459,4101) ""(4459,4626) ""(4459,4710) ""(4459,5058) ""(4460,1848) ""(4460,4187) ""(4461,513) ""(4461,2101) ""(4462,1152) ""(4462,1323) ""(4462,5728) ""(4463,4530) ""(4464,4360) ""(4465,3749) ""(4466,3925) ""(4466,4011) ""(4466,4273) ""(4467,3492) ""(4468,2369) ""(4469,4968) ""(4470,3171) ""(4472,665) ""(4472,4885) ""(4472,5146) ""(4473,837) ""(4473,2454) ""(4473,4447) ""(4474,634) ""(4474,699) ""(4474,1411) ""(4474,2152) ""(4475,733) ""(4475,766) ""(4475,3092) ""(4476,2188) ""(4476,2220) ""(4476,2250) ""(4477,1936) ""(4477,4792) ""(4478,804) ""(4482,1760) ""(4483,1240) ""(4484,894) ""(4485,487) ""(4486,2276) ""(4487,5224) ""(4488,1593) ""(4489,3456) ""(4490,609) ""(4494,1068) ""(4496,2091) ""(4496,5271) ""(4496,5759) ""(4498,1568) ""(4498,3064) ""(4498,3840) ""(4500,2400) ""(4500,3141) ""(4500,5059) ""(4501,3665) ""(4502,1391) ""(4502,1424) ""(4502,4711) ""(4503,1913) ""(4503,4189) ""(4505,1949) ""(4505,4530) ""(4505,5554) ""(4505,5583) ""(4506,2487) ""(4506,3272) ""(4506,3419) ""(4506,5339) ""(4506,5523) ""(4506,5615) ""(4507,1042) ""(4507,3371) ""(4507,3751) ""(4507,5306) ""(4507,5432) ""(4507,5492) ""(4508,1220) ""(4508,2298) ""(4508,3322) ""(4508,5370) ""(4508,5401) ""(4508,5461) ""(4508,5655) ""(4510,1740) ""(4511,3578) ""(4511,4016) ""(4511,4361) ""(4511,4792) ""(4511,4884) ""(4511,5143) ""(4513,582) ""(4513,909) ""(4513,1777) ""(4514,3925) ""(4514,4445) ""(4514,4968) ""(4515,4271) ""(4515,4623) ""(4517,4100) ""(4519,3234) ""(4520,1266) ""(4524,1091) ""(4526,5047) ""(4526,5223) ""(4527,1446) ""(4527,2068) ""(4528,1620) ""(4528,1971) ""(4529,1545) ""(4529,1893) ""(4531,1715) ""(4532,1014) ""(4532,1364) ""(4532,1799) ""(4532,5681) ""(4533,1192) ""(4533,2320) ""(4534,2437) ""(4536,560) ""(4538,939) ""(4538,1293) ""(4538,4176) ""(4539,3497) ""(4540,1124) ""(4540,1647) ""(4540,2003) ""(4541,2038) ""(4542,1330) ""(4542,1510) ""(4542,1829) ""(4543,1472) ""(4543,1863) ""(4543,4545) ""(4545,977) ""(4545,1157) ""(4545,4717) ""(4545,5066) ""(4546,1681) ""(4546,2482) ""(4546,3651) ""(4546,4892) ""(4547,3208) ""(4547,3848) ""(4551,881) ""(4552,3997) ""(4553,4026) ""(4555,1395) ""(4555,1428) ""(4555,2111) ""(4555,4345) ""(4555,4863) ""(4556,1576) ""(4556,1772) ""(4556,2345) ""(4557,847) ""(4557,913) ""(4557,1044) ""(4557,1076) ""(4557,1741) ""(4557,1917) ""(4558,1954) ""(4559,536) ""(4559,1218) ""(4559,1254) ""(4559,1607) ""(4559,2082) ""(4559,4375) ""(4559,4516) ""(4559,5707) ""(4560,4690) ""(4562,2139) ""(4562,4201) ""(4562,5209) ""(4565,3680) ""(4565,5034) ""(4566,1545) ""(4568,1367) ""(4569,1710) ""(4569,1882) ""(4570,1013) ""(4570,1801) ""(4570,1979) ""(4570,3818) ""(4572,1186) ""(4572,1285) ""(4572,1461) ""(4574,1112) ""(4574,2052) ""(4574,3180) ""(4574,4567) ""(4574,4909) ""(4575,1639) ""(4576,826) ""(4576,3523) ""(4576,3868) ""(4576,4154) ""(4577,945) ""(4577,3628) ""(4579,5089) ""(4580,486) ""(4580,4318) ""(4580,4739) ""(4580,4839) ""(4581,3973) ""(4582,2369) ""(4582,4051) ""(4582,4398) ""(4583,517) ""(4583,2165) ""(4583,4492) ""(4583,4660) ""(4584,4229) ""(4584,5006) ""(4585,5186) ""(4586,3788) ""(4587,1519) ""(4588,3711) ""(4590,1826) ""(4591,4121) ""(4591,4938) ""(4592,990) ""(4592,3903) ""(4592,3942) ""(4592,4597) ""(4592,5679) ""(4593,3557) ""(4593,3595) ""(4593,4087) ""(4593,4290) ""(4593,4971) ""(4594,1305) ""(4594,2033) ""(4594,4427) ""(4594,5157) ""(4595,1340) ""(4595,1861) ""(4595,4628) ""(4595,4776) ""(4595,4808) ""(4595,5123) ""(4596,1686) ""(4596,4463) ""(4597,3214) ""(4597,3748) ""(4597,4259) ""(4599,1161) ""(4600,1658) ""(4602,1134) ""(4602,2003) ""(4604,812) ""(4606,2394) ""(4609,965) ""(4609,1488) ""(4609,2181) ""(4612,517) ""(4617,5651) ""(4620,548) ""(4621,696) ""(4622,576) ""(4622,605) ""(4622,665) ""(4623,637) ""(4623,756) ""(4623,2273) ""(4623,2335) ""(4623,2368) ""(4624,726) ""(4624,786) ""(4624,2305) ""(4627,1318) ""(4627,2241) ""(4627,3242) ""(4630,3851) ""(4631,4008) ""(4631,5227) ""(4632,3670) ""(4632,5066) ""(4633,2014) ""(4633,4353) ""(4633,4715) ""(4633,5034) ""(4634,3481) ""(4634,4168) ""(4634,4550) ""(4634,4898) ""(4635,4203) ""(4635,4516) ""(4635,4864) ""(4636,886) ""(4636,3881) ""(4637,1408) ""(4637,4678) ""(4638,1061) ""(4638,1584) ""(4638,1932) ""(4638,3806) ""(4638,4391) ""(4639,1235) ""(4639,1758) ""(4639,3522) ""(4639,3631) ""(4640,4315) ""(4640,5188) ""(4640,5265) ""(4641,1841) ""(4641,4051) ""(4641,5625) ""(4641,5747) ""(4642,1666) ""(4642,4930) ""(4643,2103) ""(4643,3441) ""(4643,5098) ""(4644,3706) ""(4644,3962) ""(4645,1144) ""(4645,4749) ""(4646,2213) ""(4646,4584) ""(4646,4832) ""(4648,4236) ""(4648,4479) ""(4650,973) ""(4651,3268) ""(4651,4127) ""(4652,2187) ""(4653,4649) ""(4653,5001) ""(4654,1495) ""(4654,3905) ""(4656,1322) ""(4656,3147) ""(4656,3598) ""(4658,3772) ""(4661,3554) ""(4661,4422) ""(4661,5292) ""(4663,2467) ""(4664,4286) ""(4664,4950) ""(4664,5158) ""(4664,5722) ""(4665,5123) ""(4666,4078) ""(4668,888) ""(4668,4603) ""(4669,3938) ""(4669,5600) ""(4670,3734) ""(4672,4777) ""(4672,4810) ""(4673,1411) ""(4674,2017) ""(4677,1234) ""(4677,1583) ""(4678,1759) ""(4678,3413) ""(4678,4259) ""(4678,4454) ""(4681,1669) ""(4682,4631) ""(4684,1934) ""(4684,4974) ""(4685,859) ""(4685,972) ""(4685,1844) ""(4685,4107) ""(4687,1063) ""(4687,1148) ""(4688,2106) ""(4688,2193) ""(4688,3178) ""(4688,3296) ""(4688,5699) ""(4689,1495) ""(4691,2433) ""(4691,3084) ""(4691,5578) ""(4693,1324) ""(4694,3578) ""(4694,5308) ""(4698,722) ""(4699,655) ""(4699,2511) ""(4700,623) ""(4700,690) ""(4701,592) ""(4701,757) ""(4701,827) ""(4701,891) ""(4701,2328) ""(4701,2383) ""(4702,791) ""(4702,2293) ""(4703,559) ""(4703,4798) ""(4704,522) ""(4708,3925) ""(4708,5145) ""(4710,4879) ""(4710,5677) ""(4711,1418) ""(4711,4012) ""(4712,4708) ""(4713,4530) ""(4714,3329) ""(4714,3488) ""(4714,4961) ""(4714,5054) ""(4714,5228) ""(4714,5549) ""(4715,1242) ""(4715,3662) ""(4715,4184) ""(4716,4358) ""(4717,3208) ""(4717,3400) ""(4717,3748) ""(4717,3836) ""(4717,4275) ""(4717,5332) ""(4717,5455) ""(4717,5776) ""(4718,3365) ""(4718,5395) ""(4718,5426) ""(4718,5485) ""(4719,3113) ""(4719,5517) ""(4720,5363) ""(4721,2116) ""(4722,2266) ""(4722,4445) ""(4724,4623) ""(4725,1597) ""(4725,4102) ""(4728,1218) ""(4728,1567) ""(4729,1394) ""(4729,1768) ""(4730,2479) ""(4731,1950) ""(4732,544) ""(4732,1043) ""(4732,1914) ""(4734,4786) ""(4735,5652) ""(4737,439) ""(4737,1737) ""(4737,2084) ""(4738,906) ""(4739,1084) ""(4739,5754) ""(4740,3575) ""(4743,3239) ""(4745,4537) ""(4746,4879) ""(4747,1265) ""(4748,1442) ""(4749,2134) ""(4750,3146) ""(4751,5056) ""(4752,2243) ""(4753,1621) ""(4754,3486) ""(4755,4186) ""(4755,5221) ""(4756,1189) ""(4756,1364) ""(4756,1540) ""(4756,4360) ""(4756,4706) ""(4757,4971) ""(4758,571) ""(4758,3838) ""(4759,1016) ""(4759,1705) ""(4759,1882) ""(4759,2054) ""(4759,3748) ""(4759,5628) ""(4761,1807) ""(4761,1980) ""(4761,3924) ""(4761,5143) ""(4762,468) ""(4762,3663) ""(4762,4015) ""(4763,940) ""(4763,1116) ""(4763,2446) ""(4764,4272) ""(4765,1297) ""(4765,5247) ""(4765,5729) ""(4766,1475) ""(4766,3265) ""(4766,4442) ""(4767,1332) ""(4767,1508) ""(4767,2018) ""(4768,1154) ""(4768,2168) ""(4768,3056) ""(4768,4101) ""(4769,1661) ""(4769,2209) ""(4769,4623) ""(4770,980) ""(4770,1846) ""(4775,4798) ""(4776,3454) ""(4778,1761) ""(4778,3175) ""(4780,2952) ""(4781,5602) ""(4783,4882) ""(4786,598) ""(4788,491) ""(4788,5271) ""(4788,5706) ""(4789,3489) ""(4791,3079) ""(4791,4534) ""(4791,5059) ""(4791,5223) ""(4792,3292) ""(4794,2413) ""(4795,4187) ""(4796,3428) ""(4796,4362) ""(4798,1715) ""(4798,3394) ""(4798,3838) ""(4798,4443) ""(4798,5373) ""(4798,5405) ""(4798,5438) ""(4799,3575) ""(4799,4005) ""(4799,5140) ""(4799,5304) ""(4799,5343) ""(4799,5470) ""(4799,5503) ""(4799,5536) ""(4800,3360) ""(4800,4707) ""(4801,1077) ""(4801,1216) ""(4801,1247) ""(4801,1403) ""(4801,3748) ""(4802,883) ""(4802,1044) ""(4802,3324) ""(4802,3922) ""(4803,1566) ""(4803,1604) ""(4803,1913) ""(4804,3204) ""(4805,915) ""(4805,1437) ""(4805,1798) ""(4805,1950) ""(4805,4270) ""(4805,4621) ""(4805,4967) ""(4806,4101) ""(4807,850) ""(4808,4792) ""(4809,623) ""(4811,2301) ""(4811,3664) ""(4812,1370) ""(4813,1105) ""(4813,1188) ""(4813,3100) ""(4813,5570) ""(4813,5682) ""(4816,522) ""(4816,1012) ""(4816,1279) ""(4816,1536) ""(4817,2970) ""(4819,1878) ""(4820,1636) ""(4820,1981) ""(4821,1466) ""(4821,4872) ""(4822,1686) ""(4825,945) ""(4826,3225) ""(4826,4017) ""(4829,822) ""(4829,2378) ""(4830,1832) ""(4830,5219) ""(4831,3493) ""(4832,645) ""(4832,1165) ""(4833,1343) ""(4835,1130) ""(4836,4711) ""(4836,5658) ""(4838,3123) ""(4840,1305) ""(4840,4369) ""(4841,4543) ""(4841,5540) ""(4842,544) ""(4843,990) ""(4843,1511) ""(4843,3849) ""(4843,4193) ""(4843,5067) ""(4844,4893) ""(4848,1660) ""(4849,2007) ""(4849,5037) ""(4850,3001) ""(4850,3244) ""(4850,3645) ""(4850,3992) ""(4851,1485) ""(4852,3815) ""(4854,1855) ""(4855,963) ""(4855,4163) ""(4855,4334) ""(4856,3143) ""(4856,4511) ""(4857,3681) ""(4857,5635) ""(4859,4856) ""(4860,672) ""(4862,1329) ""(4863,3516) ""(4863,4039) ""(4863,4680) ""(4863,5199) ""(4864,1147) ""(4865,5519) ""(4866,805) ""(4866,2337) ""(4867,775) ""(4868,571) ""(4868,4738) ""(4869,709) ""(4869,2112) ""(4869,2303) ""(4870,743) ""(4870,2081) ""(4870,2273) ""(4872,2145) ""(4872,2176) ""(4872,2209) ""(4872,2241) ""(4873,4572) ""(4874,4920) ""(4876,3272) ""(4876,3963) ""(4876,5096) ""(4877,3612) ""(4877,3783) ""(4878,3029) ""(4878,4407) ""(4879,3710) ""(4879,3884) ""(4879,4229) ""(4879,5003) ""(4880,4304) ""(4880,4475) ""(4880,4822) ""(4881,3167) ""(4881,5612) ""(4882,1061) ""(4882,1235) ""(4882,2053) ""(4882,5169) ""(4883,1758) ""(4883,1931) ""(4883,4647) ""(4884,888) ""(4884,1585) ""(4884,4116) ""(4885,5134) ""(4886,4074) ""(4886,4266) ""(4886,4786) ""(4886,4964) ""(4887,3562) ""(4887,5498) ""(4888,3926) ""(4889,1410) ""(4889,2012) ""(4889,3748) ""(4890,4612) ""(4891,591) ""(4892,969) ""(4892,1664) ""(4893,1494) ""(4893,1843) ""(4893,4444) ""(4896,4879) ""(4896,5029) ""(4897,1145) ""(4897,3996) ""(4897,4537) ""(4897,5069) ""(4899,2903) ""(4899,3655) ""(4899,4031) ""(4899,4687) ""(4900,1319) ""(4900,3297) ""(4900,3468) ""(4900,4141) ""(4900,4191) ""(4900,4357) ""(4902,3512) ""(4902,3825) ""(4902,3862) ""(4902,4734) ""(4903,3692) ""(4904,3191) ""(4904,5588) ""(4905,2032) ""(4907,3058) ""(4907,4395) ""(4908,4320) ""(4908,4921) ""(4909,4576) ""(4909,4839) ""(4910,4490) ""(4913,3787) ""(4915,3955) ""(4916,615) ""(4916,1238) ""(4916,1761) ""(4916,1935) ""(4916,3433) ""(4916,3612) ""(4918,4067) ""(4919,886) ""(4919,1064) ""(4921,4766) ""(4922,4647) ""(4923,3550) ""(4924,2925) ""(4925,5118) ""(4926,3323) ""(4927,3727) ""(4927,4989) ""(4929,1587) ""(4929,3214) ""(4929,3904) ""(4929,5568) ""(4930,1413) ""(4932,971) ""(4932,4424) ""(4933,1668) ""(4933,4290) ""(4933,4808) ""(4933,4947) ""(4934,1844) ""(4934,2017) ""(4934,4464) ""(4937,637) ""(4937,857) ""(4937,1148) ""(4937,1495) ""(4937,3762) ""(4938,1319) ""(4939,4604) ""(4940,3090) ""(4940,3416) ""(4942,4100) ""(4944,5439) ""(4946,760) ""(4946,4260) ""(4947,793) ""(4947,826) ""(4947,892) ""(4947,2193) ""(4947,2324) ""(4948,727) ""(4948,2224) ""(4948,2259) ""(4949,696) ""(4949,3931) ""(4950,1938) ""(4950,2128) ""(4950,2293) ""(4950,2788) ""(4951,664) ""(4951,2158) ""(4952,2099) ""(4952,3349) ""(4953,3239) ""(4953,3581) ""(4954,2932) ""(4956,5135) ""(4957,1242) ""(4957,1759) ""(4961,1067) ""(4963,4441) ""(4966,1593) ""(4967,5419) ""(4969,1400) ""(4969,3012) ""(4970,4792) ""(4971,3753) ""(4972,1920) ""(4972,3123) ""(4973,3404) ""(4973,4971) ""(4976,4187) ""(4977,3264) ""(4977,3836) ""(4977,4358) ""(4980,3372) ""(4980,3485) ""(4980,3662) ""(4980,4010) ""(4980,4880) ""(4981,1216) ""(4981,4532) ""(4981,4624) ""(4981,5054) ""(4982,1426) ""(4983,906) ""(4983,1565) ""(4983,4706) ""(4983,5264) ""(4983,5295) ""(4984,1740) ""(4984,5229) ""(4984,5397) ""(4985,2084) ""(4985,5328) ""(4988,2785) ""(4988,5362) ""(4989,1041) ""(4990,5197) ""(4991,1768) ""(4992,1086) ""(4993,2933) ""(4993,5138) ""(4994,1959) ""(4997,1265) ""(4997,1376) ""(4997,4272) ""(4998,1614) ""(4999,1898) ""(5000,3153) ""(5002,3045) ""(5003,3288) ""(5004,1714) ""(5005,4099) ""(5005,5490) ""(5007,1191) ""(5007,4796) ""(5008,1535) ""(5010,1461) ""(5010,1804) ""(5010,2058) ""(5010,3928) ""(5011,1009) ""(5012,934) ""(5012,5165) ""(5013,1347) ""(5013,1992) ""(5013,4181) ""(5014,1872) ""(5014,4014) ""(5015,1118) ""(5015,1647) ""(5017,1305) ""(5017,2027) ""(5017,3837) ""(5017,4448) ""(5017,5056) ""(5018,1155) ""(5018,1502) ""(5018,1680) ""(5018,3494) ""(5018,4703) ""(5019,3660) ""(5019,4530) ""(5020,1840) ""(5020,3577) ""(5021,972) ""(5021,4357) ""(5021,4876) ""(5024,3751) ""(5025,4621) ""(5026,2784) ""(5027,5468) ""(5028,3313) ""(5029,3467) ""(5030,3180) ""(5033,2932) ""(5035,4970) ""(5036,5141) ""(5037,3080) ""(5048,4010) ""(5048,5447) ""(5051,3494) ""(5051,4100) ""(5051,4180) ""(5053,3338) ""(5053,3446) ""(5054,4796) ""(5058,2783) ""(5058,3660) ""(5060,3210) ""(5061,4703) ""(5062,4269) ""(5062,4351) ""(5062,5265) ""(5062,5300) ""(5062,5332) ""(5063,5366) ""(5063,5395) ""(5064,2932) ""(5064,3925) ""(5064,4877) ""(5064,5231) ""(5065,3417) ""(5065,3832) ""(5065,5423) ""(5066,3378) ""(5066,4447) ""(5066,4529) ""(5066,4618) ""(5066,5050) ""(5068,3751) ""(5069,3575) ""(5072,4970) ""(5074,3113) ""(5074,5144) ""(5083,4191) ""(5085,3494) ""(5087,4003) ""(5088,3238) ""(5089,4363) ""(5091,2782) ""(5093,3655) ""(5095,4700) ""(5098,2933) ""(5098,5221) ""(5101,4891) ""(5102,3823) ""(5103,4519) ""(5103,4545) ""(5103,5066) ""(5106,3851) ""(5108,4169) ""(5108,4865) ""(5109,3151) ""(5111,4028) ""(5111,5040) ""(5112,4724) ""(5113,3677) ""(5113,4342) ""(5115,3266) ""(5116,4203) ""(5119,3510) ""(5119,3990) ""(5120,4380) ""(5122,3640) ""(5123,2948) ""(5124,2782) ""(5128,4681) ""(5128,5202) ""(5130,3804) ""(5130,4561) ""(5132,4499) ""(5132,5084) ""(5133,4151) ""(5135,3872) ""(5136,4320) ""(5136,4845) ""(5136,4915) ""(5138,3966) ""(5138,4746) ""(5138,5013) ""(5139,4053) ""(5140,3618) ""(5140,3703) ""(5140,4230) ""(5142,2860) ""(5142,3182) ""(5143,4404) ""(5145,4659) ""(5145,5179) ""(5146,3541) ""(5147,2969) ""(5147,4124) ""(5148,4292) ""(5148,4590) ""(5149,3777) ""(5149,4813) ""(5150,3738) ""(5150,3902) ""(5150,3936) ""(5150,4091) ""(5150,4468) ""(5150,4781) ""(5151,3585) ""(5151,4263) ""(5151,5118) ""(5152,3301) ""(5152,4623) ""(5153,4435) ""(5153,4948) ""(5153,4981) ""(5153,5150) ""(5155,2783) ""(5173,2995) ""(5175,3215) ""(5176,2885) ""(5182,3332) ""(5190,2785) ""(5196,3018) ""(5197,2864) ""(5200,2909) ""(5206,3247) ""(5211,3361) ""(5217,3040) ""(5221,2783) ""(5226,2933) ""(5228,2864) ""(5236,3061) ""(5241,3283) ""(5245,3395) ""(5248,2955) ""(5256,2783) ""(5257,3080) ""(5261,2864) ""(5270,2980) ""(5272,3315) ""(5274,3423) ""(5277,3099) ""(5292,2785) ""(5292,2864) ""(5295,3004) ""(5298,3120) ""(5301,3452) ""(5308,3349) ""(5317,3026) ""(5317,3141) ""(5324,2870) ""(5330,2786) ""(5330,3481) ""(5338,3048) ""(5339,3383) ""(5340,3160) ""(5348,2893) ""(5357,3068) ""(5359,3179) ""(5359,3509) ""(5371,2781) ""(5371,2915) ""(5371,3417) ""(5376,2809) ""(5379,3090) ""(5379,3199) ""(5387,3537) ""(5392,2938) ""(5398,3219) ""(5399,2834) ""(5400,3110) ""(5401,3446) ""(5409,2778) ""(5413,2957) ""(5416,3565) ""(5419,3132) ""(5419,3239) ""(5422,2856) ""(5435,2979) ""(5435,3478) ""(5439,3151) ""(5440,2779) ""(5440,3258) ""(5444,2879) ""(5444,3593) ""(5460,3171) ""(5461,3003) ""(5461,3280) ""(5467,2899) ""(5469,3620) ""(5470,2778) ""(5471,3512) ""(5481,3193) ""(5483,3302) ""(5485,3029) ""(5488,2922) ""(5499,3543) ""(5502,3655) ""(5503,3215) ""(5504,2781) ""(5504,3322) ""(5510,2942) ""(5512,3054) ""(5523,3235) ""(5527,3346) ""(5530,3572) ""(5531,2966) ""(5532,2801) ""(5533,3687) ""(5534,3078) ""(5545,3257) ""(5550,3369) ""(5553,2988) ""(5556,2823) ""(5558,3600) ""(5561,3104) ""(5566,3713) ""(5568,3281) ""(5573,2729) ""(5575,3393) ""(5576,3010) ""(5580,2844) ""(5585,3626) ""(5587,3130) ""(5591,3303) ""(5595,2750) ""(5597,3417) ""(5600,3032) ""(5602,2867) ""(5608,3714) ""(5612,3156) ""(5612,3326) ""(5613,2769) ""(5621,3055) ""(5622,3441) ""(5624,2888) ""(5626,3632) ""(5634,2792) ""(5636,3180) ""(5636,3347) ""(5642,3075) ""(5643,2905) ""(5645,3718) ""(5646,3466) ""(5656,2811) ""(5658,3367) ""(5660,3203) ""(5661,2924) ""(5664,3094) ""(5664,3634) ""(5669,3489) ""(5677,2831) ""(5679,2945) ""(5681,3716) ""(5682,3391) ""(5684,3227) ""(5687,3120) ""(5694,3513) ""(5698,2965) ""(5699,2851) ""(5701,3634) ""(5706,3416) ""(5708,3140) ""(5708,3250) ""(5718,3539) ""(5719,2871) ""(5720,2989) ""(5721,3717) ""(5727,3163) ""(5728,3440) ""(5732,3274) ""(5737,2893) ""(5738,3634) ""(5742,3009) ""(5743,3562) ""(5749,3183) ""(5751,3461) ""(5755,3298) ""(5758,2913) ""(5762,3028) ""(5762,3717) ""(5770,3204) ""(5772,3485) ""(5774,3595) ""(5775,3633) ""(5777,3322) ""(5779,2936) ""(5783,3049) ""(5790,3223) ""(5797,3511) ""(5800,2956) ""(5803,3071) ""(5803,3347) ""(5806,3719) ""(5810,3245) ""(5819,2976) ""(5823,3093) ""(5823,3532) ""(5827,3370) ""(5832,3264) ""(5841,2996) ""(5846,3114) ""(5851,3393) ""(5852,3286) ""(5855,3719) ""(5857,3638) ""(5860,3560) ""(5861,3017) ""(5867,3134) ""(5874,3305) ""(5875,3420) ""(5882,3036) ""(5889,3156) ""(5895,3561) ""(5896,3330) ""(5897,3716) ""(5898,3444) ""(5900,3637) ""(5901,3059) ""(5909,3177) ""(5918,3466) ""(5919,3352) ""(5923,3079) ""(5930,3560) ""(5931,3198) ""(5936,3715) ""(5939,3487) ""(5940,3372) ""(5945,3099) ""(5955,3220) ""(5960,3393) ""(5961,3507) ""(5962,3559) ""(5965,3119) ""(5975,3714) ""(5976,3240) ""(5981,3414) ""(5984,3139) ""(5985,3535) ""(5997,3261) ""(6002,3159) ""(6003,3433) ""(6013,3714) ""(6019,3286) ""(6022,3177) ""(6022,3454) ""(6041,3197) ""(6041,3474) ""(6043,3308) ""(6051,3712) ""(6063,3217) ""(6064,3330) ""(6069,3477) ""(6084,3239) ""(6085,3713) ""(6086,3353) ""(6100,3477) ""(6103,3259) ""(6108,3378) ""(6120,3714) ""(6124,3278) ""(6134,3478) ""(6141,3297) ""(6161,3713) ""(6162,3431) ""(6165,3318) ""(6173,3476) ""(6183,3448) ""(6203,3713) ""(6209,3477) ""(6226,3379) ""(6238,3713) ""(6251,3404) ""(6274,3419) ""(6276,3712) ""(6305,3419) ""(6311,3710) ""(6338,3689) ""(6339,3420) ""(6364,3674) ""(6374,3408)

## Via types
v1: diameter 24, hole 12, Top Layer to Bottom Layer, tented both sides, 141 vias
